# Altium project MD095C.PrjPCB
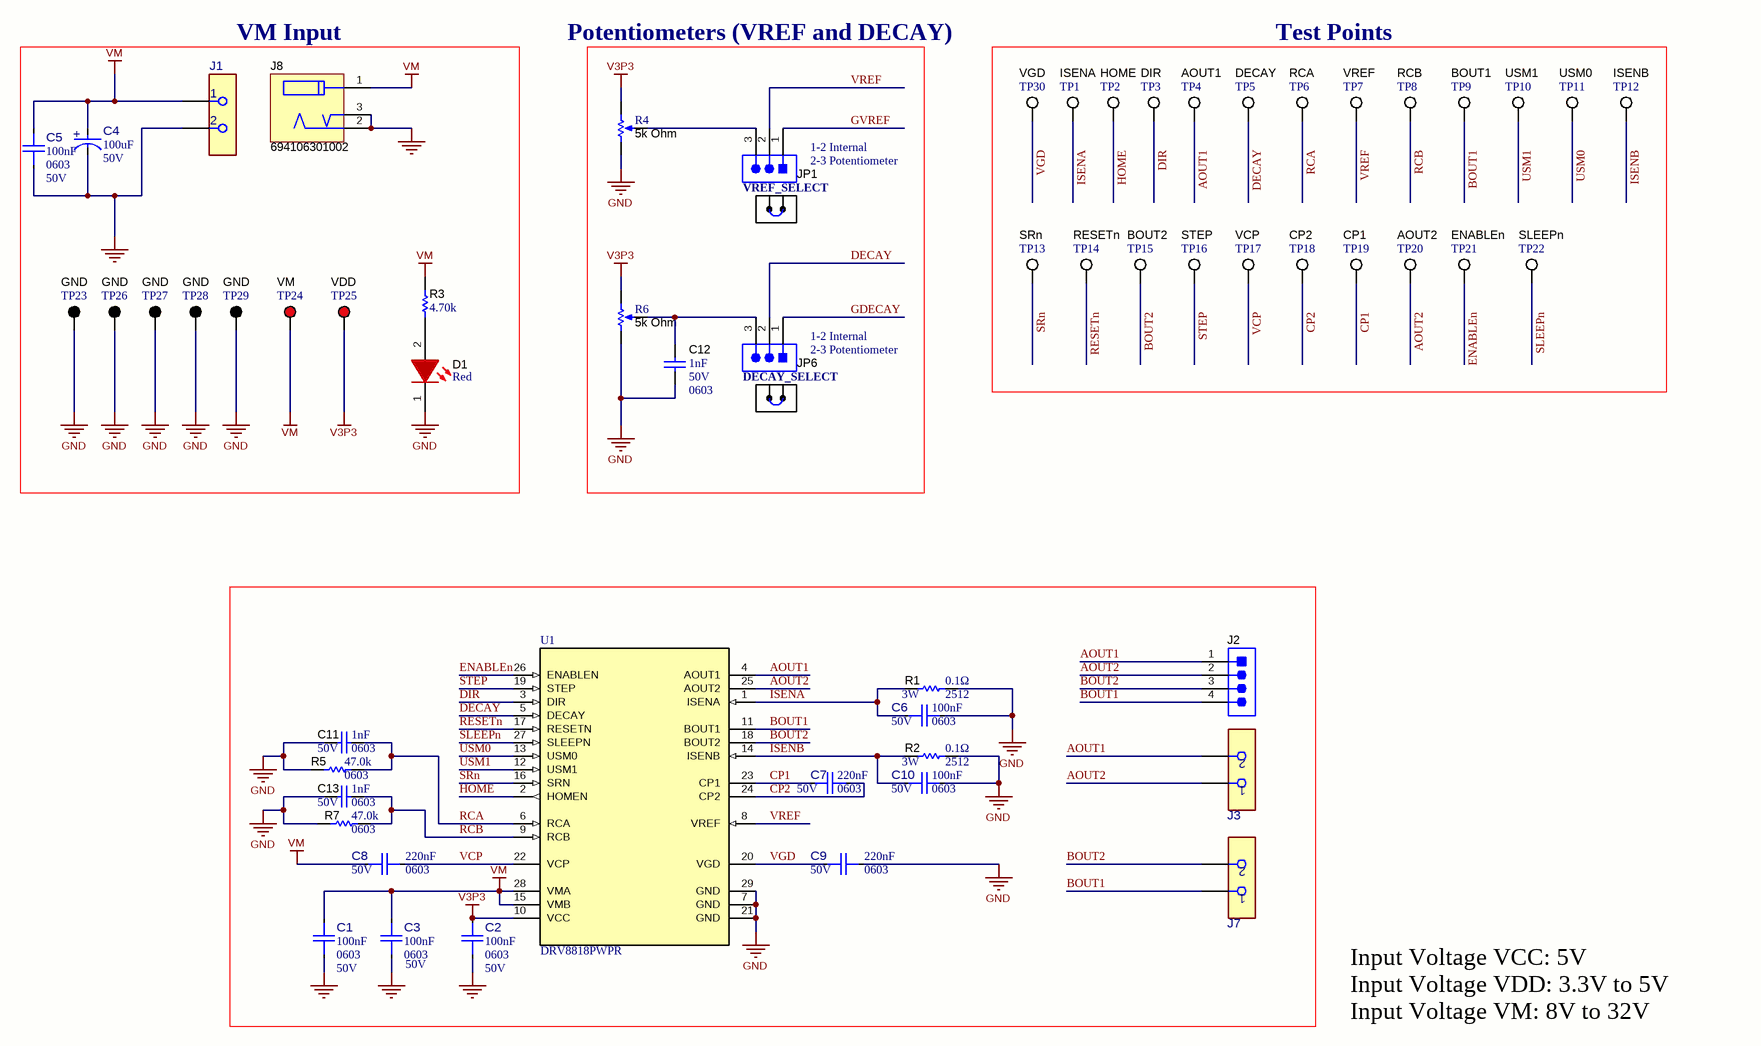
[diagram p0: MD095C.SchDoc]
CopyrightYear: 2024; PCB_Layout: Jacob Thompson; PCB_Rev: C; PRJ_Customer: Public Release; PRJ_Engineer: Jacob Thompson; PRJ_Number: MD095; PRJ_Number_and_Rev: MD095C; PRJ_Title: DRV8818EVM; SCH_Rev: C; TechSupport: http://www.ti.com/support; TID: N/A
3 sheets, 146 parts. Net scope: global (net labels, ports and power ports of the same name join across sheets).
Board file: MD095C.PcbDoc
Sheets:
  MD095C.SchDoc
  MD095C_Hardware.SchDoc
  MD095C_MSP430.SchDoc

## Sheet MD095C.SchDoc
size 431 x 279 mm; Date: Not shown in title block; ApprovedBy: Not shown in title block; CheckedBy: Not shown in title block; Author: Not shown in title block; CompanyName: Not shown in title block; DrawnBy: Jacob Thompson; Engineer: Not shown in title block; Organization: Not shown in title block; Address1: Not shown in title block; Address2: Not shown in title block; Address3: Not shown in title block; Address4: Not shown in title block; DocumentNumber: 1; Revision: C; SheetNumber: 1; SheetTotal: 3; PageSetup: Record=PageOptions¦CenterHorizontal=True¦CenterVertical=True¦PrintScale=1.00¦XCorrection=1.00¦YCorrection=1.00¦PrintKind=0¦BorderSize=5000000¦LeftOffset=0¦BottomOffset=0¦Orientation=2¦PaperLength=1000¦PaperWidth=1000¦Scale=100¦PaperSource=15¦PrintQuality=600¦MediaType=1¦DitherType=10¦PaperKind=Letter¦PrintScaleMode=1

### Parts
C1  Cap_F: 100nF  PackageReference: 0603  VDC_V: 50V  [FP-885012206095_0603-MFG]  (hidden comment: 885012206095)
C2  Cap_F: 100nF  PackageReference: 0603  VDC_V: 50V  [FP-885012206095_0603-MFG]  (hidden comment: 885012206095)
C3  Cap_F: 100nF  PackageReference: 0603  VDC_V: 50V  [FP-885012206095_0603-MFG]  (hidden comment: 885012206095)
C4  ValueDisplayed: 100uF  VDC_V: 50V  [FP-865080653016_SMT_CAP_8MM3_8MM3-MFG]  (hidden comment: 865080653016)
C5  Cap_F: 100nF  PackageReference: 0603  VDC_V: 50V  [FP-885012206095_0603-MFG]  (hidden comment: 885012206095)
C6  Cap_F: 100nF  PackageReference: 0603  VDC_V: 50V  [FP-885012206095_0603-MFG]  (hidden comment: 885012206095)
C7  Cap_F: 220nF  PackageReference: 0603  VDC_V: 50V  [FP-885012206125_0603-MFG]  (hidden comment: 885012206125)
C8  Cap_F: 220nF  PackageReference: 0603  VDC_V: 50V  [FP-885012206125_0603-MFG]  (hidden comment: 885012206125)
C9  Cap_F: 220nF  PackageReference: 0603  VDC_V: 50V  [FP-885012206125_0603-MFG]  (hidden comment: 885012206125)
C10  Cap_F: 100nF  PackageReference: 0603  VDC_V: 50V  [FP-885012206095_0603-MFG]  (hidden comment: 885012206095)
C11  Cap_F: 1nF  VDC_V: 50V  [0603]  (hidden comment: 885012206083)
C12  Cap_F: 1nF  VDC_V: 50V  [0603]  (hidden comment: 885012206083)
C13  Cap_F: 1nF  VDC_V: 50V  [0603]  (hidden comment: 885012206083)
D1  value Red  [WL-SMCW_RED_0805]  (hidden comment: 150080RS75000)
J1  691250610002  [FP-691250610002_CONN_TERM_BLOCK2-MFG]  (value not drawn)
J2  61300411121  [WURTH_61300411121]  (value not drawn)
J3  691250610002  [FP-691250610002_CONN_TERM_BLOCK2-MFG]  (value not drawn)
J7  691250610002  [FP-691250610002_CONN_TERM_BLOCK2-MFG]  (value not drawn)
J8  694106301002  [Wurth_694106301002]
JP1  61300311121  [WURTH_61300311121]  (value not drawn)
JP6  61300311121  [WURTH_61300311121]  (value not drawn)
R1  Value2: 3W  ValueDisplayed: 0.1Ω  [2512]  (hidden comment: CRA2512-FZ-R100ELF)
R2  Value2: 3W  ValueDisplayed: 0.1Ω  [2512]  (hidden comment: CRA2512-FZ-R100ELF)
R3  ValueDisplayed: 4.70k  [0603]  (hidden comment: RC0603FR-074K7L)
R4  value 5k Ohm  [Bourns_PV37W]  (hidden comment: PV37W502C01B00)
R5  ValueDisplayed: 47.0k  [0603]  (hidden comment: RC0603FR-0747KL)
R6  value 5k Ohm  [Bourns_PV37W]  (hidden comment: PV37W502C01B00)
R7  ValueDisplayed: 47.0k  [0603]  (hidden comment: RC0603FR-0747KL)
SH-JP1  60900213421  [Wurth_60900213421]  (value not drawn)
SH-JP6  60900213421  [Wurth_60900213421]  (value not drawn)
TP1  ISENA  [Keystone5012]
TP2  HOME  [Keystone5012]
TP3  DIR  [Keystone5012]
TP4  AOUT1  [Keystone5012]
TP5  DECAY  [Keystone5012]
TP6  RCA  [Keystone5012]
TP7  VREF  [Keystone5012]
TP8  RCB  [Keystone5012]
TP9  BOUT1  [Keystone5012]
TP10  USM1  [Keystone5012]
TP11  USM0  [Keystone5012]
TP12  ISENB  [Keystone5012]
TP13  SRn  [Keystone5012]
TP14  RESETn  [Keystone5012]
TP15  BOUT2  [Keystone5012]
TP16  STEP  [Keystone5012]
TP17  VCP  [Keystone5012]
TP18  CP2  [Keystone5012]
TP19  CP1  [Keystone5012]
TP20  AOUT2  [Keystone5012]
TP21  ENABLEn  [Keystone5012]
TP22  SLEEPn  [Keystone5012]
TP23  GND  [Keystone5011]
TP24  VM  [Keystone5010]
TP25  VDD  [Keystone5010]
TP26  GND  [Keystone5011]
TP27  GND  [Keystone5011]
TP28  GND  [Keystone5011]
TP29  GND  [Keystone5011]
TP30  VGD  [Keystone5012]
U1  PartNumber: DRV8818PWPR  [PWP0028D_L]  (hidden comment: DRV8818PWP)

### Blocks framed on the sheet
VM Input: C4 C5 D1 J1 J8 R3 TP23-TP29
Test Points: TP1-TP22 TP30

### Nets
GND: C1.1 C2.1 C3.1 C4.1(CATHODE) C5.1 C6.2 C9.2 C10.2 C11.2 C12.2 C13.2 D1.1(K) J1.2 J8.2 J8.3 R1.2 R2.2 R4.1(CCW) R5.1 R6.1(CCW) R7.1 TP23.1 TP26.1 TP27.1 TP28.1 TP29.1 U1.7(GND) U1.21(GND) U1.29(GND)
V3P3: C2.2 R4.3(CW) R6.3(CW) TP25.1 U1.10(VCC)
VM: C1.2 C3.2 C4.2(ANODE) C5.2 C8.1 J1.1 J8.1 R3.1 TP24.1 U1.15(VMB) U1.28(VMA)
AOUT1: J2.1 J3.2 TP4.1 U1.4(AOUT1)
AOUT2: J2.2 J3.1 TP20.1 U1.25(AOUT2)
BOUT1: J2.4 J7.1 TP9.1 U1.11(BOUT1)
BOUT2: J2.3 J7.2 TP15.1 U1.18(BOUT2)
CP1: C7.2 TP19.1 U1.23(CP1)
CP2: C7.1 TP18.1 U1.24(CP2)
DECAY: JP6.2 TP5.1 U1.5(DECAY)
DIR: TP3.1 U1.3(DIR)
ENABLEn: TP21.1 U1.26(ENABLEN)
GDECAY: JP6.1
GVREF: JP1.1
HOME: TP2.1 U1.2(HOMEN)
ISENA: C6.1 R1.1 TP1.1 U1.1(ISENA)
ISENB: C10.1 R2.1 TP12.1 U1.14(ISENB)
RCA: C11.1 R5.2 TP6.1 U1.6(RCA)
RCB: C13.1 R7.2 TP8.1 U1.9(RCB)
RESETn: TP14.1 U1.17(RESETN)
SLEEPn: TP22.1 U1.27(SLEEPN)
SRn: TP13.1 U1.16(SRN)
STEP: TP16.1 U1.19(STEP)
USM0: TP11.1 U1.13(USM0)
USM1: TP10.1 U1.12(USM1)
VCP: C8.2 TP17.1 U1.22(VCP)
VGD: C9.1 TP30.1 U1.20(VGD)
VREF: JP1.2 TP7.1 U1.8(VREF)
NetC12_1: C12.1 JP6.3 R6.2(WIPER)
NetD1_2: D1.2(A) R3.2
NetJP1_3: JP1.3 R4.2(WIPER)

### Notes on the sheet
- Potentiometers (VREF and DECAY)
- (near SH-JP1) VREF_SELECT
- (near JP1) 1-2 Internal
- (near JP1) 2-3 Potentiometer
- (near JP6) 1-2 Internal
- (near SH-JP6) DECAY_SELECT
- (near JP6) 2-3 Potentiometer
- Input Voltage VCC: 5V
- Input Voltage VDD: 3.3V to 5V
- Input Voltage VM: 8V to 32V

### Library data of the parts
C1-C3 C5 C6 C10 = CMP-0049204-1: 0.1 µF ±10% 50V Ceramic Capacitor X7R 0603 (1608 Metric); Manufacturer: Wurth; AEC Qualified: No; SizeZ_mm: 0.87mm; TempCo: 15%; Value: 100nF
C4 = CMP-0097307-1: 100 µF 50 V Aluminum Electrolytic Capacitors Radial, Can - SMD 2000 Hrs @ 105°C; Manufacturer: Wurth Electronics; Tolerance_%: 20%; SizeZ_mm: 10.5mm; IRMS_A: 350mA; AEC Qualified: No; Value: 100µF; Dissipation Factor: 12%; Leakage Current: 50uA; Life: 2000Hours
C7-C9 = CMP-0049212-1: 0.22 µF ±5% 50V Ceramic Capacitor X7R 0603 (1608 Metric); Manufacturer: Wurth Electronics; AEC Qualified: No; SizeZ_mm: 0.95mm; TempCo: 15%; Value: 220nF
C11-C13 = CMP-0064933-4: CAP, CERM, 1000 pF, 50 V,+/- 10%, X7R, 0603; Manufacturer: Wurth Elektronik; TaMin_C: -55°C; Polarized: N; SizeAreaWB_mm2: 4.68; Value1: Unknown; U/M: EA; Value: 1000pF; TaMax_C: 125°C; SizeZ_mm: 1; SizeX_mm: 1.6; SizeY_mm: 0.8; SizeArea_mm2: 1.28; AEC Category: Q200
D1 = CMP-0077509-2: LED, Red, SMD; Manufacturer: Wurth Elektronik; Type: AlInGaP; Value2: 2V; Ir_A: 10µA; Power_TotalModule: 72mW; Vr_V: 5V; Value1: 0.072W; Angle: 140.0; Io_A: 20mA
J1 J3 J7 = CMP-0093233-2: 2 Position Wire to Board Terminal Block Horizontal with Board 0.250" (6.35mm) Through Hole; Manufacturer: Wurth Electronics; Current_A: 32A; Conn Gender: Female; Row_Count: 1; ContactFinish: Zinc; SizeZ_mm: 21.6mm; Max Wire Gauge: 10; Min Wire Gauge: 30; Voltage_V: 450V; AEC Qualified: No; Is Female: yes
J2 = CMP-0054798-2: Header, 2.54 mm, 4x1, Gold, TH; Manufacturer: Wurth Elektronik; Pitch_mm: 2.54; Gender: Male; Row_Count: 1; Cert_UL: Y; Shrouded: N
J8 = CMP-0054778-4: WR-DC DC Power Jack, R/A, TH; Manufacturer: Wurth Elektronik; Gender: Male
JP1 JP6 = CMP-0054796-4: Header, 2.54 mm, 3x1, Gold, TH; Manufacturer: Wurth Elektronik; Green_Lifecycle: Active; Green_REACh: Passed; CT: FALSE; CNHeader: TRUE
R1 R2 = CMP-0015426-3: RES, 0.1, 1%, 3 W, 2512; Manufacturer: Bourns; SizeX_mm: 6.3; SizeY_mm: 3.2; SizeZ_mm: 0.71; AEC Qualified: Y; Value: 0.1; SizeArea_mm2: 20.16; AEC Category: Q200; U/M: EA; VDC_V: 1V; TempCo: 50 ppm/C; AEC Grade: 0; Value_Code: R100; EIA_Code: E96; Res_ohm: 1d
R3 = CMP-0023153-5: RES, 4.70 k, 1%, 0.1 W, 0603; Manufacturer: Yageo; Power_W: 100mW; TempCo: 100 ppm/C; Value_Code: 4k70; Value: 4.70k; Res_ohm: 4.7k; SizeX_mm: 1.6; SizeY_mm: 0.8; SizeZ_mm: 1; Value2: 0.1W; SizeArea_mm2: 1.28; AEC Qualified: N; VDC_V: 75V; AEC Category: Q200; SizeAreaWB_mm2: 4.68
R4 R6 = CMP-0001795-2: Trimmer Potentiometer, Lead Sealed Type Multiturn PV37 Series, TH; Manufacturer: Bourns; SizeX_mm: 6.71; SizeY_mm: 4.5; SizeZ_mm: 8.39; SizeArea_mm2: 30.195; SizeAreaWB_mm2: 56.615
R5 R7 = CMP-0023133-5: RES, 47.0 k, 1%, 0.1 W, 0603; Manufacturer: Yageo; Power_W: 100mW; TempCo: 100 ppm/C; Value_Code: 47k0; Value: 47.0k; Res_ohm: 47k; SizeX_mm: 1.6; SizeY_mm: 0.8; SizeZ_mm: 1; Value2: 0.1W; SizeArea_mm2: 1.28; AEC Qualified: N; VDC_V: 75V; AEC Category: Q200; SizeAreaWB_mm2: 4.68
SH-JP1 SH-JP6 = CMP-0003761-2: Shunt, 2.54mm, Gold, Black; Manufacturer: Wurth Elektronik
TP1-TP22 TP30 = CMP-0055149-2: Test Point, Multipurpose, White, TH; Manufacturer: Keystone Electronics; ContactFinish: Silver; CT: TRUE; CNHeader: FALSE; Green_Lifecycle: Active; Green_REACh: Passed
TP23 TP26-TP29 = CMP-0055148-2: Test Point, Multipurpose, Black, TH; Manufacturer: Keystone Electronics; PartNumber: 36-5011-ND; CNHeader: FALSE; Green_Lifecycle: Active; Green_REACh: Passed; ContactFinish: Silver; CT: TRUE
TP24 TP25 = CMP-0055147-2: Test Point, Multipurpose, Red, TH; Manufacturer: Keystone Electronics; PartNumber: 36-5010-ND; CNHeader: FALSE; Green_Lifecycle: Active; Green_REACh: Passed; ContactFinish: Silver; CT: TRUE
U1 = CMP-0029877-2: 2.5 A Bipolar Stepper Motor Driver with On-Chip 1/8 MicroStepping Indexer (Step / Dir Ctrl), 8 to 35 V, -40 to 85 degC, 28-pin SOP (PWP28), Green (RoHS & no Sb/Br); Manufacturer: Texas Instruments; Peak Output Current(A): 2.5; RMS Output Current(A): 1.75; Vs(Max)(V): 35; Vs(Min)(V): 8; rDS (ON) (LS + HS)(mOhms): 370

## Sheet MD095C_Hardware.SchDoc
size 431 x 279 mm; Date: Not shown in title block; ApprovedBy: Not shown in title block; CheckedBy: Not shown in title block; Author: Not shown in title block; CompanyName: Not shown in title block; DrawnBy: Jacob Thompson; Engineer: Not shown in title block; Organization: Not shown in title block; Address1: Not shown in title block; Address2: Not shown in title block; Address3: Not shown in title block; Address4: Not shown in title block; DocumentNumber: 3; Revision: C; SheetNumber: 3; SheetTotal: 3; PageSetup: Record=PageOptions¦CenterHorizontal=True¦CenterVertical=True¦PrintScale=1.00¦XCorrection=1.00¦YCorrection=1.00¦PrintKind=0¦BorderSize=5000000¦LeftOffset=0¦BottomOffset=0¦Orientation=2¦PaperLength=1000¦PaperWidth=1000¦Scale=100¦PaperSource=15¦PrintQuality=600¦MediaType=1¦DitherType=10¦PaperKind=Letter¦PrintScaleMode=1
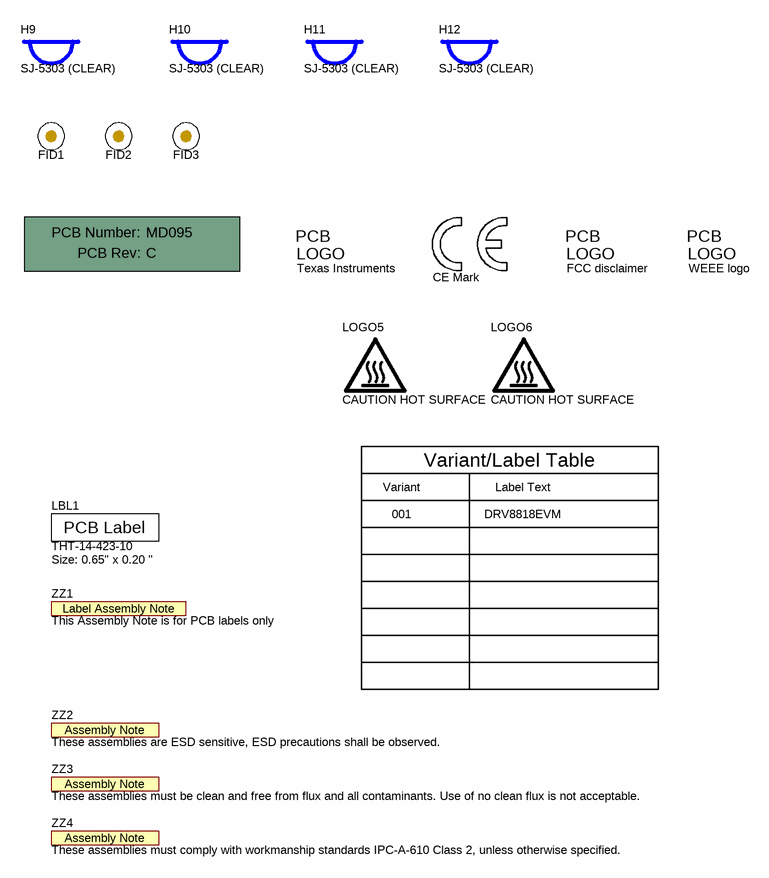
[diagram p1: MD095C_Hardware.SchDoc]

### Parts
!PCB  Printed Circuit Board  (value not drawn)  (mechanical)
FID1  Fiducial  [Fiducial10-20]  (value not drawn)  (no BOM)
FID2  Fiducial  [Fiducial10-20]  (value not drawn)  (no BOM)
FID3  Fiducial  [Fiducial10-20]  (value not drawn)  (no BOM)
H9  SJ-5303 (CLEAR)  [Bumpon_SJ5003Transparent]
H10  SJ-5303 (CLEAR)  [Bumpon_SJ5003Transparent]
H11  SJ-5303 (CLEAR)  [Bumpon_SJ5003Transparent]
H12  SJ-5303 (CLEAR)  [Bumpon_SJ5003Transparent]
LBL1  THT-14-423-10  Note: Size: 0.65" x 0.20 "  [Label_650x200]
Logo1  Texas Instruments  [TI_Stacked_Overlay_Small]  (no BOM)
Logo2  CE Mark  [CE_Mark_5mm]  (no BOM)
Logo3  FCC disclaimer  [FCC_disclaimer]  (no BOM)
Logo4  WEEE logo  [WEEE_Minimum]  (no BOM)
LOGO5  CAUTION HOT SURFACE  [IEC_HotSurface_Small]  (no BOM)
LOGO6  CAUTION HOT SURFACE  [IEC_HotSurface_Small]  (no BOM)
ZZ1  This Assembly Note is for PCB labels only  [AssemblyNoteLabel]  (no BOM)
ZZ2  These assemblies are ESD sensitive, ESD precautions shall be observed.  [AssemblyNote]  (no BOM)
ZZ3  These assemblies must be clean and free from flux and all contaminants. Use of no clean flux is not acceptable.  [AssemblyNote]  (no BOM)
ZZ4  These assemblies must comply with workmanship standards IPC-A-610 Class 2, unless otherwise specified.  [AssemblyNote]  (no BOM)

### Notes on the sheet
- Variant
- Variant/Label Table
- Label Text
- 001
- DRV8818EVM

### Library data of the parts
!PCB = CMP-0003618-2: Manufacturer: Any; PartNumber: MD095
FID1-FID3 = CMP-0077181-1: Fiducial mark.  There is nothing to buy or mount.
H9-H12 = CMP-0003620-1: Bumpon, Hemisphere, 0.44 X 0.20, Clear; Manufacturer: 3M
LBL1 = CMP-0003625-1: Thermal Transfer Printable Labels, 0.650" W x 0.200" H - 10,000 per roll; Manufacturer: Brady; CompType: Label
Logo1 = CMP-0074838-1: Texas Instrument Corporate Signature; SymbolCreator: a0412235; Lib Reference: TI_Logo; Library Reference: Logo
Logo2 = CMP-0074844-2: Manufacturer: Texas Instruments; SymbolCreator: a0412235; AEC Category: Q200; CompType: IC
Logo3 = CMP-0074847-1: FCC_disclaimer; Library Reference: Logo
Logo4 = CMP-0074769-4: Manufacturer: Texas Instruments; CompType: IC; AEC Category: Q200
LOGO5 LOGO6 = CMP-0074837-2: IEC 61010-1 Hot Surface Warning; Manufacturer: Texas Instruments; SymbolCreator: a0412235; CompType: IC; AEC Category: Q200
ZZ1 = CMP-0003616-3
ZZ2 = CMP-0077236-1
ZZ3 = CMP-0077237-1
ZZ4 = CMP-0077238-1

## Sheet MD095C_MSP430.SchDoc
size 431 x 279 mm; Date: Not shown in title block; ApprovedBy: Not shown in title block; CheckedBy: Not shown in title block; Author: Not shown in title block; CompanyName: Not shown in title block; DrawnBy: Jacob Thompson; Engineer: Not shown in title block; Organization: Not shown in title block; Address1: Not shown in title block; Address2: Not shown in title block; Address3: Not shown in title block; Address4: Not shown in title block; DocumentNumber: 2; Revision: C; SheetNumber: 2; SheetTotal: 3; PageSetup: Record=PageOptions¦CenterHorizontal=True¦CenterVertical=True¦PrintScale=1.00¦XCorrection=1.00¦YCorrection=1.00¦PrintKind=0¦BorderSize=5000000¦LeftOffset=0¦BottomOffset=0¦Orientation=2¦PaperLength=1000¦PaperWidth=1000¦Scale=100¦PaperSource=15¦PrintQuality=600¦MediaType=1¦DitherType=10¦PaperKind=Letter¦PrintScaleMode=1
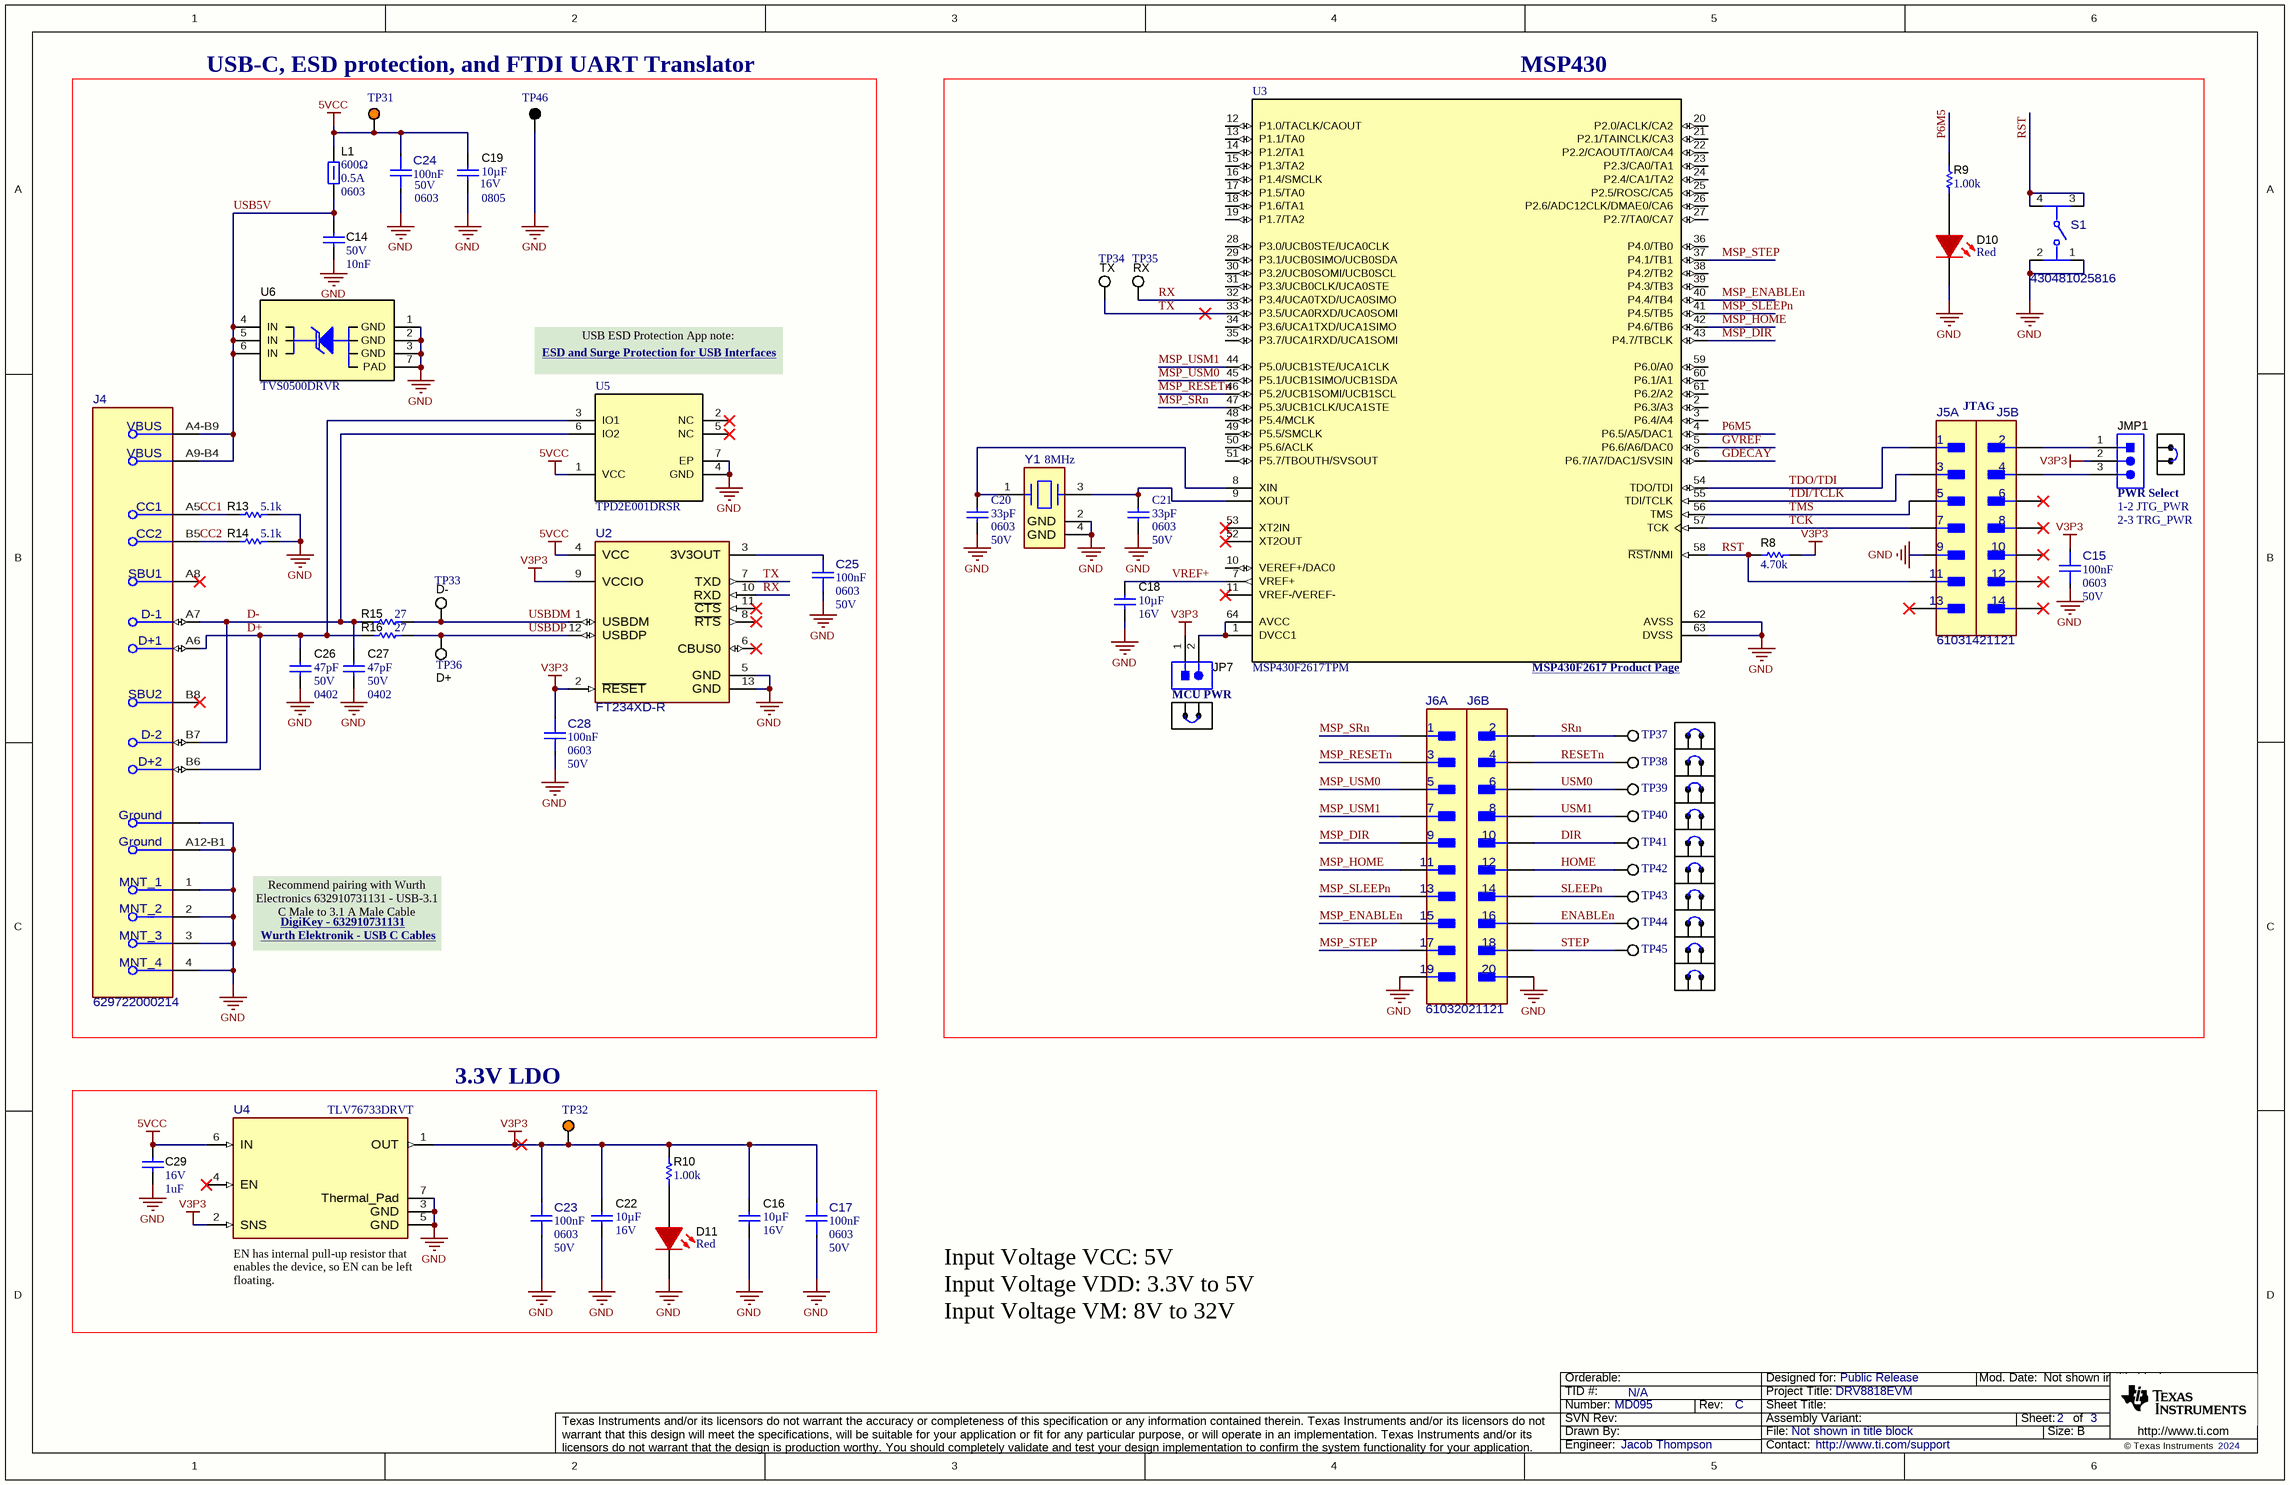
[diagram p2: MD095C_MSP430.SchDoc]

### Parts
C14  VDC_V: 50V  Cap_F: 10nF  [0603]  (hidden comment: 885012206089)
C15  Cap_F: 100nF  PackageReference: 0603  VDC_V: 50V  [FP-885012206095_0603-MFG]  (hidden comment: 885012206095)
C16  VDC_V: 16V  ValueDisplayed: 10µF  [0805_150]  (hidden comment: 885012107014)
C17  Cap_F: 100nF  PackageReference: 0603  VDC_V: 50V  [FP-885012206095_0603-MFG]  (hidden comment: 885012206095)
C18  VDC_V: 16V  ValueDisplayed: 10µF  [0805_150]  (hidden comment: 885012107014)
C19  PackageReference: 0805  VDC_V: 16V  ValueDisplayed: 10µF  [0805_150]  (hidden comment: 885012107014)
C20  value 33pF  PackageReference: 0603  Rated Voltage (DC): 50V  [WCAP-CSGP_0603_L1.6W0.8H0.8_Reflow]  (hidden comment: 885012006054)
C21  value 33pF  PackageReference: 0603  Rated Voltage (DC): 50V  [WCAP-CSGP_0603_L1.6W0.8H0.8_Reflow]  (hidden comment: 885012006054)
C22  VDC_V: 16V  ValueDisplayed: 10µF  [0805_150]  (hidden comment: 885012107014)
C23  Cap_F: 100nF  PackageReference: 0603  VDC_V: 50V  [FP-885012206095_0603-MFG]  (hidden comment: 885012206095)
C24  Cap_F: 100nF  PackageReference: 0603  VDC_V: 50V  [FP-885012206095_0603-MFG]  (hidden comment: 885012206095)
C25  Cap_F: 100nF  PackageReference: 0603  VDC_V: 50V  [FP-885012206095_0603-MFG]  (hidden comment: 885012206095)
C26  VDC_V: 50V  ValueDisplayed: 47pF  [0402]  (hidden comment: 885012005044)
C27  VDC_V: 50V  ValueDisplayed: 47pF  [0402]  (hidden comment: 885012005044)
C28  Cap_F: 100nF  PackageReference: 0603  VDC_V: 50V  [FP-885012206095_0603-MFG]  (hidden comment: 885012206095)
C29  VDC_V: 16V  ValueDisplayed: 1uF  [0603]  (hidden comment: 885012106017)
D10  value Red  [WL-SMCW_RED_0805]  (hidden comment: 150080RS75000)
D11  value Red  [WL-SMCW_RED_0805]  (hidden comment: 150080RS75000)
J4  629722000214  [FP-629722000214_CONN_USB-MFG]
J5  61031421121  [FP-61031421121_HDR14-MFG]  (value not drawn)  (parts A,B of 2)
J6  61032021121  [FP-61032021121_HDR20-MFG]  (parts A,B of 2)
JMP1  61300311121  [WURTH_61300311121]  (value not drawn)
JP7  61300211121  [WURTH_61300211121]  (value not drawn)
L1  Value2: 0.5A  ValueDisplayed: 600Ω  [0603]  (hidden comment: 742863160)
R8  ValueDisplayed: 4.70k  [0603]  (hidden comment: RC0603FR-074K7L)
R9  ValueDisplayed: 1.00k  [0603]  (hidden comment: RC0603FR-071KL)
R10  ValueDisplayed: 1.00k  [0603]  (hidden comment: RC0603FR-071KL)
R13  ValueDisplayed: 5.1k  [0603]  (hidden comment: RC0603JR-075K1L)
R14  ValueDisplayed: 5.1k  [0603]  (hidden comment: RC0603JR-075K1L)
R15  ValueDisplayed: 27  [0603]  (hidden comment: CRCW060327R0JNEA)
R16  ValueDisplayed: 27  [0603]  (hidden comment: CRCW060327R0JNEA)
S1  430481025816  [FP-430481025816_SMT_SW_6MM2_6MM2-MFG]
SH-J1  60900213421  [Wurth_60900213421]  (value not drawn)
SH-J2  60900213421  [Wurth_60900213421]  (value not drawn)
SH-J3  60900213421  [Wurth_60900213421]  (value not drawn)
SH-J4  60900213421  [Wurth_60900213421]  (value not drawn)
SH-J5  60900213421  [Wurth_60900213421]  (value not drawn)
SH-J6  60900213421  [Wurth_60900213421]  (value not drawn)
SH-J7  60900213421  [Wurth_60900213421]  (value not drawn)
SH-J8  60900213421  [Wurth_60900213421]  (value not drawn)
SH-J9  60900213421  [Wurth_60900213421]  (value not drawn)
SH-J10  60900213421  [Wurth_60900213421]  (value not drawn)
SH-JMP1  60900213421  [Wurth_60900213421]  (value not drawn)
SH-JP7  60900213421  [Wurth_60900213421]  (value not drawn)
TP31  5V  [Keystone5003]  (value not drawn)
TP32  3.3V  [Keystone5003]  (value not drawn)
TP33  D-  [Keystone5002]
TP34  TX  [Keystone5002]
TP35  RX  [Keystone5002]
TP36  D+  [Keystone5002]
TP37  5002  [Keystone5002]  (value not drawn)
TP38  5002  [Keystone5002]  (value not drawn)
TP39  5002  [Keystone5002]  (value not drawn)
TP40  5002  [Keystone5002]  (value not drawn)
TP41  5002  [Keystone5002]  (value not drawn)
TP42  5002  [Keystone5002]  (value not drawn)
TP43  5002  [Keystone5002]  (value not drawn)
TP44  5002  [Keystone5002]  (value not drawn)
TP45  5002  [Keystone5002]  (value not drawn)
TP46  GND  [Keystone5011]  (value not drawn)
U2  FT234XD-R  [FP-FT234XD-R_DFN-12-MFG]
U3  MSP430F2617TPM  [PM0064A_L]
U4  TLV76733DRVT  [DRV0006A-MFG]
U5  TPD2E001DRSR  [DRS0006A]
U6  TVS0500DRVR  [DRV0006A]
Y1  Frequency_Fixed: 8MHz  [FP-830055663_SMT_CRYSTAL_5MM0_3MM2-MFG]  (hidden comment: 830055663)

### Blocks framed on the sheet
USB-C, ESD protection, and FTDI UART Translator: C14 C19 C24-C28 J4 L1 R13-R16 TP31 TP33 TP36 TP46 U2 U5 U6
MSP430: C15 C18 C20 C21 D10 J5 J6 JMP1 JP7 R8 R9 S1 SH-J1-SH-J10 SH-JMP1 SH-JP7 TP34 TP35 TP37-TP45 U3 Y1
3.3V LDO: C16 C17 C22 C23 C29 D11 R10 TP32 U4

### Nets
5VCC: C19.1 C24.1 C29.2 L1.2 TP31.1 U2.4(VCC) U4.6(IN) U5.1(VCC)
GND: C14.2 C15.2 C16.2 C17.1 C18.2 C19.2 C20.1 C21.1 C22.2 C23.1 C24.2 C25.1 C26.2 C27.2 C28.2 C29.1 D10.1(K) D11.1(K) J4.1(MNT_1) J4.2(MNT_2) J4.3(MNT_3) J4.4(MNT_4) J4.A1-B12(Ground) J4.A12-B1(Ground) J5.9 J6.19 J6.20 R13.2 R14.2 S1.1 S1.2 TP46.1 U2.5(GND) U2.13(GND) U3.62(AVSS) U3.63(DVSS) U4.3(GND) U4.5(GND) U4.7(Thermal_Pad) U5.4(GND) U5.7(EP) U6.1(GND) U6.2(GND) U6.3(GND) U6.7(PAD) Y1.2(GND) Y1.4(GND)
V3P3: C15.1 C16.1 C17.2 C22.1 C23.2 C28.1 JMP1.2 JP7.1 R8.1 R10.2 TP32.1 U2.2(~{RESET}) U2.9(VCCIO) U4.1(OUT) U4.2(SNS)
CC1: J4.A5(CC1) R13.1
CC2: J4.B5(CC2) R14.1
D+: C26.1 J4.A6(D+1) J4.B6(D+2) R16.1 U5.3(IO1)
D-: C27.1 J4.A7(D-1) J4.B7(D-2) R15.1 U5.6(IO2)
DIR: J6.10 TP41.1
ENABLEn: J6.16 TP44.1
GDECAY: U3.6(P6.7/A7/DAC1/SVSIN)
GVREF: U3.5(P6.6/A6/DAC0)
HOME: J6.12 TP42.1
MSP_DIR: J6.9 U3.43(P4.7/TBCLK)
MSP_ENABLEn: J6.15 U3.40(P4.4/TB4)
MSP_HOME: J6.11 U3.42(P4.6/TB6)
MSP_RESETn: J6.3 U3.46(P5.2/UCB1SOMI/UCB1SCL)
MSP_SLEEPn: J6.13 U3.41(P4.5/TB5)
MSP_SRn: J6.1 U3.47(P5.3/UCB1CLK/UCA1STE)
MSP_STEP: J6.17 U3.37(P4.1/TB1)
MSP_USM0: J6.5 U3.45(P5.1/UCB1SIMO/UCB1SDA)
MSP_USM1: J6.7 U3.44(P5.0/UCB1STE/UCA1CLK)
P6M5: R9.2 U3.4(P6.5/A5/DAC1)
RESETn: J6.4 TP38.1
RST: J5.11 R8.2 S1.3 S1.4 U3.58(~{RST}/NMI)
RX: TP35.1 U2.10(RXD) U3.32(P3.4/UCA0TXD/UCA0SIMO)
SLEEPn: J6.14 TP43.1
SRn: J6.2 TP37.1
STEP: J6.18 TP45.1
TCK: J5.7 U3.57(TCK)
TDI/TCLK: J5.3 U3.55(TDI/TCLK)
TDO/TDI: J5.1 U3.54(TDO/TDI)
TMS: J5.5 U3.56(TMS)
TX: TP34.1 U2.7(TXD) U3.33(P3.5/UCA0RXD/UCA0SOMI)
USB5V: C14.1 J4.A4-B9(VBUS) J4.A9-B4(VBUS) L1.1 U6.4(IN) U6.5(IN) U6.6(IN)
USBDM: R15.2 TP33.1 U2.1(USBDM)
USBDP: R16.2 TP36.1 U2.12(USBDP)
USM0: J6.6 TP39.1
USM1: J6.8 TP40.1
VREF+: C18.1 U3.7(VREF+)
NetC20_2: C20.2 U3.8(XIN) Y1.1(1_Crystal)
NetC21_2: C21.2 U3.9(XOUT) Y1.3(2_Crystal)
NetC25_2: C25.2 U2.3(3V3OUT)
NetD10_2: D10.2(A) R9.1
NetD11_2: D11.2(A) R10.1
NetJ5_2: J5.2 JMP1.1
NetJ5_4: J5.4 JMP1.3
NetJP7_2: JP7.2 U3.1(DVCC1) U3.64(AVCC)

Not connected (* = marked no-connect by the designer): J4 A8(SBU1)* B8(SBU2)*; J5 6* 8* 10* 12* 13* 14*; U2 6(CBUS0)* 8(~{RTS})* 11(~{CTS})*; U3 2(P6.3/A3) 3(P6.4/A4) 10(VEREF+/DAC0) 11(VREF-/VEREF-)* 12(P1.0/TACLK/CAOUT) 13(P1.1/TA0) 14(P1.2/TA1) 15(P1.3/TA2) 16(P1.4/SMCLK) 17(P1.5/TA0) 18(P1.6/TA1) 19(P1.7/TA2) 20(P2.0/ACLK/CA2) 21(P2.1/TAINCLK/CA3) 22(P2.2/CAOUT/TA0/CA4) 23(P2.3/CA0/TA1) 24(P2.4/CA1/TA2) 25(P2.5/ROSC/CA5) 26(P2.6/ADC12CLK/DMAE0/CA6) 27(P2.7/TA0/CA7) 28(P3.0/UCB0STE/UCA0CLK) 29(P3.1/UCB0SIMO/UCB0SDA) 30(P3.2/UCB0SOMI/UCB0SCL) 31(P3.3/UCB0CLK/UCA0STE) 34(P3.6/UCA1TXD/UCA1SIMO) 35(P3.7/UCA1RXD/UCA1SOMI) 36(P4.0/TB0) 38(P4.2/TB2) 39(P4.3/TB3) 48(P5.4/MCLK) 49(P5.5/SMCLK) 50(P5.6/ACLK) 51(P5.7/TBOUTH/SVSOUT) 52(XT2OUT)* 53(XT2IN)* 59(P6.0/A0) 60(P6.1/A1) 61(P6.2/A2); U4 4(EN)*; U5 2(NC)* 5(NC)*

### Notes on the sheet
- ESD and Surge Protection for USB Interfaces <https://www.ti.com/lit/an/slvaf82b/slvaf82b.pdf>
- (near U5) USB ESD Protection App note:
- (near J5) JTAG
- (near JMP1) PWR Select
- 1-2 JTG_PWR
- 2-3 TRG_PWR
- (near SH-JP7) MCU PWR
- (near U3) MSP430F2617 Product Page <https://www.ti.com/product/MSP430F2617>
- Recommend pairing with Wurth Electronics 632910731131 - USB-3.1 C Male to 3.1 A Male Cable
- Wurth Elektronik - USB C Cables <https://www.we-online.com/en/components/products/COM_3_1_CAB_ASSEMBLIES>
- DigiKey - 632910731131 <https://www.digikey.com/en/products/detail/w%C3%BCrth-elektronik/632910731131/5723517>
- Input Voltage VCC: 5V
- Input Voltage VDD: 3.3V to 5V
- (near U4) EN has internal pull-up resistor that enables the device, so EN can be left floating.
- Input Voltage VM: 8V to 32V

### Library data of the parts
C14 = CMP-0750039-1: CAP, CERM, 0.01 µF, 50 V,+/- 10%, X7R, 0603; Manufacturer: Wurth Elektronik; Polarized: N; AEC Category: Q200; TaMax_C: 125°C; SizeAreaWB_mm2: 4.68; Value: 0.01uF; SizeArea_mm2: 1.28; SizeY_mm: 0.8; SizeZ_mm: 1; ValueDisplayed: 0.01µF; SizeX_mm: 1.6; U/M: EA; TaMin_C: -55°C
C15 C17 C23-C25 C28 = CMP-0049204-1: as C1 on sheet MD095C
C16 C18 C22 = CMP-0078154-1: CAP, CERM, 10 µF, 16 V,+/- 20%, X5R, 0805; Manufacturer: Wurth Elektronik; TaMin_C: -55°C; Polarized: N; SizeAreaWB_mm2: 6.75; U/M: EA; Value: 10uF; TaMax_C: 85°C; SizeZ_mm: 1.5; SizeX_mm: 2; SizeY_mm: 1.25; Cap_Case: 0805; SizeArea_mm2: 2.5; AEC Category: Q200
C19 = CMP-0078154-1: CAP, CERM, 10 µF, 16 V,+/- 20%, X5R, 0805; Manufacturer: Wurth Elektronik; TaMin_C: -55°C; Polarized: N; SizeAreaWB_mm2: 6.75; U/M: EA; Value: 10uF; TaMax_C: 85°C; SizeZ_mm: 1.5; SizeX_mm: 2; SizeY_mm: 1.25; SizeArea_mm2: 2.5; AEC Category: Q200
C20 C21 = CMP-0107798-1: WCAP-CSGP Multilayer Ceramic Chip Capacitor, General Purpose, size 0603, NP0, 33pF, 50VDC; Manufacturer: Wurth Elektronik; Capacitance Tolerance: +/-5%; Insulation Resistance: 10GOhm; Q Factor: 1000; Technical Reference: NP00603330J050DFCT10000
C26 C27 = CMP-0006214-2: CAP, CERM, 47 pF, 50 V, +/- 5%, C0G/NP0, 0402; Manufacturer: Wurth Elektronik; TaMin_C: -55°C; Polarized: N; SizeAreaWB_mm2: 3; Value1: Unknown; U/M: EA; Value: 47pF; TaMax_C: 125°C; SizeZ_mm: 0.6; SizeX_mm: 1; SizeY_mm: 0.5; AEC Category: Q200
C29 = CMP-0006824-5: CAP, CERM, 1 uF, 16 V, +/- 20%, X5R, 0603; Manufacturer: Wurth Elektronik; TaMin_C: -55°C; Polarized: N; SizeAreaWB_mm2: 4.68; Value1: Unknown; U/M: EA; Value: 1uF; TaMax_C: 85°C; SizeZ_mm: 1; SizeX_mm: 1.6; SizeY_mm: 0.8; SizeArea_mm2: 1.28; Cap_F: 1µF; AEC Category: Q200
D10 D11 = CMP-0077509-2: as D1 on sheet MD095C
J4 = CMP-0095999-2: Conenctor USB 2.0 Type C Horizontal SMT; Manufacturer: Wurth Electronics; Current_A: 5A; ContactFinish: Gold,Nickel; AEC Qualified: No; Shrouded: true; Voltage_V: 20V; SizeZ_mm: 3.51mm; Usb Standard: USB 2.0; Is Female: yes
J5 = CMP-0122757-1: Connector Header Surface Mount 14 position 0.100" (2.54mm); Manufacturer: Wurth Electronics; ContactFinish: Gold; Current_A: 3A; Row_Count: 2; Voltage_V: 250V; AEC Qualified: No; Conn Gender: Male; Conn Orientation: Straight; SizeZ_mm: 9.9mm; Standoff Height: 0.76mm
J6 = CMP-0122703-1: Connector Header Surface Mount 20 position 0.100" (2.54mm); Manufacturer: Wurth; ContactFinish: Gold; Current_A: 3A; Row_Count: 2; Voltage_V: 250V; AEC Qualified: No; Conn Gender: Male; Conn Orientation: Straight; SizeZ_mm: 10mm
JMP1 = CMP-0054796-4: as JP1 on sheet MD095C
JP7 = CMP-0054794-2: Header, 2.54 mm, 2x1, Gold, TH; Manufacturer: Wurth Elektronik; Shrouded: N; Gender: Male; Green_REACh: Passed; Pitch_mm: 2.54; Green_Lifecycle: Active; Row_Count: 1; Cert_UL: Y
L1 = CMP-0003267-2: Ferrite Bead, 600 ohm @ 100 MHz, 0.5 A, 0603; Manufacturer: Wurth Elektronik; Ztyp@1GHz_Ohm: 997.006; ZTyp@100MHz_Ohm: 600; SizeAreaWB_mm2: 4.68; DCR_ohm: 3.5d; Value1: 0.35 ohm; Value: 600 ohm; Imax_A: 5dA; SizeZ_mm: 1; SizeX_mm: 1.6; SizeY_mm: 0.8; SizeArea_mm2: 1.28
R8 = CMP-0023153-5: as R3 on sheet MD095C
R9 R10 = CMP-0022895-5: RES, 1.00 k, 1%, 0.1 W, 0603; Manufacturer: Yageo; Power_W: 100mW; TempCo: 100 ppm/C; Value_Code: 1k00; Value: 1.00k; EIA_Code: E96; Res_ohm: 1k; SizeX_mm: 1.6; SizeY_mm: 0.8; SizeZ_mm: 1; Value2: 0.1W; SizeArea_mm2: 1.28; AEC Qualified: N; VDC_V: 75V; AEC Category: Q200; SizeAreaWB_mm2: 4.68
R13 R14 = CMP-0025932-5: RES, 5.1 k, 5%, 0.1 W, 0603; Manufacturer: Yageo; Power_W: 100mW; TempCo: 100 ppm/C; Value_Code: 5k10; Value: 5.1k; EIA_Code: E24; SizeX_mm: 1.6; SizeY_mm: 0.8; SizeZ_mm: 1; Value2: 0.1W; SizeArea_mm2: 1.28; AEC Qualified: N; VDC_V: 75V; AEC Category: Q200; SizeAreaWB_mm2: 4.68
R15 R16 = CMP-0025767-4: RES, 27, 5%, 0.1 W, AEC-Q200 Grade 0, 0603; Manufacturer: Vishay-Dale; Power_W: 100mW; TempCo: 200 ppm/C; Value_Code: 27R0; Value: 27; EIA_Code: E24; SizeX_mm: 1.6; SizeY_mm: 0.8; SizeZ_mm: 1; Value2: 0.1W; SizeArea_mm2: 1.28; AEC Qualified: Y; VDC_V: 75V; AEC Category: Q200; AEC Grade: 0
S1 = CMP-0097347-1: Tactile Switch SPST-NO Top Actuated Surface Mount; Manufacturer: Wurth Electronics; VDC_V: 12V; Electromechanical Life: 1000000Cycles; SizeZ_mm: 2.7mm; Coil Resistance_ohm: 100mΩ; Operating Force: 160gf; AEC Qualified: No; Contact Current Rating: 50mA
SH-J1-SH-J10 SH-JMP1 SH-JP7 = CMP-0003761-2: as SH-JP1 on sheet MD095C
TP31 TP32 = CMP-0055140-2: Test Point, Miniature, Orange, TH; Manufacturer: Keystone Electronics; CNHeader: FALSE; Green_Lifecycle: Active; Green_REACh: Passed; ContactFinish: Silver; CT: TRUE
TP33-TP45 = CMP-0055139-2: Test Point, Miniature, White, TH; Manufacturer: Keystone Electronics; ContactFinish: Silver; Green_REACh: Passed; CT: TRUE; Green_Lifecycle: Active; CNHeader: FALSE
TP46 = CMP-0055148-2: as TP23 on sheet MD095C
U2 = CMP-0088151-1: USB Bridge, USB to UART USB 2.0 UART Interface 12-DFN (3x3); Manufacturer: FTDI; SizeZ_mm: 0.8mm
U3 = CMP-0038674-2: 16 MHz Mixed Signal Microcontroller with 92 KB Flash, 8192 B SRAM and 48 GPIOs, -40 to 105 degC, 64-pin QFP (PM), Green (RoHS & no Sb/Br); Manufacturer: Texas Instruments; Frequency(MHz): 16; ADC: 12-bit SAR; DMA: 3; USCI_B (I2C & SPI): 2; Multiplier: 16x16; ADC Channels: 8; Comparators: Yes; GPIO: 48; Flash(KB): 92; SubFamily: 2 Series, Extended Temp; SRAM(B): 8192
U4 = CMP-0090734-1: Linear Voltage Regulator IC  1 Output  1A 6-WSON (2x2); Manufacturer: Texas Instruments; SizeZ_mm: 0.8mm; Nominal Supply Current: 60uA; TJmax_C: +125°C; Max Supply Voltage: 16V; Number Of Outputs: 1; Accuracy Percentage: 1%; Output Type: Fixed; Output Voltage: 3.3V; Standoff Height: 0mm; Dropout Voltage: 0.9V; AEC Qualified: No; Min Supply Voltage: 2.5V
U5 = CMP-0043097-2: Low-Capacitance + / - 15 kV ESD-Protection Array for High-Speed Data Interfaces, 2 Channels, -40 to +85 degC, 6-pin SON (DRS), Green (RoHS & no Sb/Br); Manufacturer: Texas Instruments; IO Leakage Current(nA): 1; IO Capacitance(Typ)(pF): 1.5; USB High Speed: TRUE; SubFamily: ESD Solution; Breakdown Voltage(Min)(V): 11; IEC 61000-4-2 Air-Gap(+/- kV): 15; IEC 61000-4-2 Contact(+/- kV): 8
U6 = CMP-0077837-1: 5-V Precision Surge Protection Clamp, DRV0006A (WSON-6); Alternate Manufacturer: Texas Instruments; SizeAreaWB_mm2: 9.0; SizeZ_mm: 0.8; SizeX_mm: 2.0; SizeArea_mm2: 4.0; CompType: IC; AEC Qualified: N; AEC Category: Q200
Y1 = CMP-0122977-1: 8 MHz ±20ppm Crystal 18pF 150 Ohms 4-SMD, No Lead; Manufacturer: Wurth; Frequency Stability: 30ppm; SizeZ_mm: 1mm; Esr: 150

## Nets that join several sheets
GND: MD095C (29 pins), MD095C_MSP430 (47 pins)
V3P3: MD095C (5 pins), MD095C_MSP430 (15 pins)
DIR: MD095C (TP3.1 U1.3), MD095C_MSP430 (J6.10 TP41.1)
ENABLEn: MD095C (TP21.1 U1.26), MD095C_MSP430 (J6.16 TP44.1)
GDECAY: MD095C (JP6.1), MD095C_MSP430 (U3.6)
GVREF: MD095C (JP1.1), MD095C_MSP430 (U3.5)
HOME: MD095C (TP2.1 U1.2), MD095C_MSP430 (J6.12 TP42.1)
RESETn: MD095C (TP14.1 U1.17), MD095C_MSP430 (J6.4 TP38.1)
SLEEPn: MD095C (TP22.1 U1.27), MD095C_MSP430 (J6.14 TP43.1)
SRn: MD095C (TP13.1 U1.16), MD095C_MSP430 (J6.2 TP37.1)
STEP: MD095C (TP16.1 U1.19), MD095C_MSP430 (J6.18 TP45.1)
USM0: MD095C (TP11.1 U1.13), MD095C_MSP430 (J6.6 TP39.1)
USM1: MD095C (TP10.1 U1.12), MD095C_MSP430 (J6.8 TP40.1)

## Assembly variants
001: not fitted FID1 FID2 FID3 TP33 TP34 TP35 TP36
